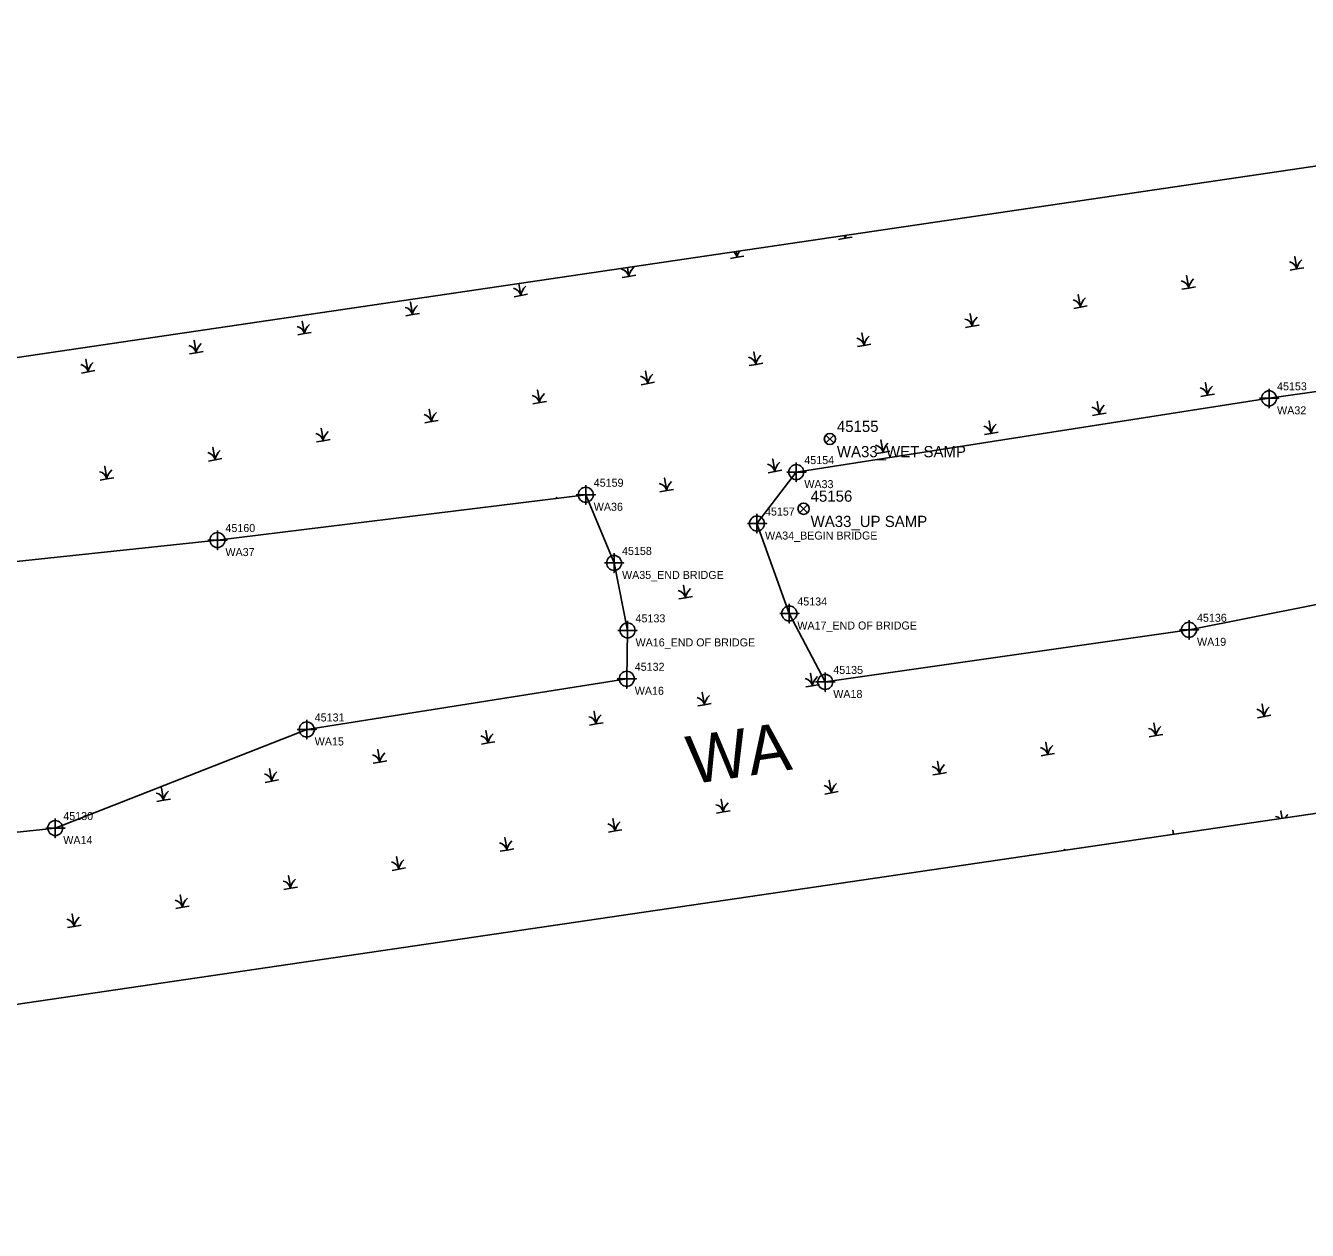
# Model space of a CAD drawing. Extents: x 2111078 to 2112659, y 581517 to 581899.
# Drawn here: x 2111868.3 to 2112268.6, y 581523.2 to 581899.2 of the extents above; entities that cross this region are included whole.
import ezdxf

# ---------------------------------------------------------------- set-up
doc = ezdxf.new("R2010")
doc.units = 0
for name, color, linetype in [('Default', 7, 'Continuous'), ('Exist Environmental Wetland Boundary', 7, 'Continuous'), ('Exist Environmental Wetland Boundary Cogo Comment', 7, 'Continuous'), ('Exist Environmental Wetland Boundary Cogo Number', 7, 'Continuous'), ('Exist Environmental Wetland Boundary Cogo Point CELL', 7, 'Continuous'), ('Exist Environmental Wetland Boundary Text', 7, 'Continuous'), ('Exist Hydro Swamp or Marsh', 7, 'Continuous')]:
    doc.layers.add(name, color=color, linetype=linetype)

msp = doc.modelspace()

# ---------------------------------------------------------------- linework, layer by layer
at = {"layer": 'Default'}
for p, q in [((2112120.71, 581771.41), (2112118.24, 581768.93)), ((2112118.24, 581771.41), (2112120.71, 581768.93)), ((2112112.51, 581749.62), (2112110.03, 581747.15)), ((2112110.03, 581749.62), (2112112.51, 581747.15))]:
    msp.add_line(p, q, dxfattribs=at)
msp.add_lwpolyline([(2111089.87, 581523.16), (2111077.52, 581722.78), (2111579.66, 581753.48), (2112568.99, 581899.18), (2112598.13, 581701.32), (2111600.4, 581554.74), (2111516.52, 581549.55)], close=True, dxfattribs=at)
for centre in [(2112119.47, 581770.17), (2112111.27, 581748.39)]:
    msp.add_circle(centre, 1.75, dxfattribs=at)
at = {"layer": 'Exist Environmental Wetland Boundary'}
for points in [[(2112579.95, 581824.73), (2112443.39, 581809.13), (2112256.64, 581782.86), (2112109, 581759.83), (2112096.72, 581743.78), (2112106.82, 581715.7), (2112118.04, 581694.33), (2112231.63, 581710.61), (2112367.17, 581737.55), (2112425.86, 581731.24), (2112435.22, 581709.75), (2112484.9, 581686.89), (2112506.03, 581692.11), (2112548.3, 581765.77), (2112570.44, 581765.42), (2112537.9, 581733.37), (2112525.65, 581690.67)], [(2111819.27, 581586.89), (2111826.15, 581643.33), (2111877.59, 581648.73), (2111956.11, 581679.5), (2112056.05, 581695.32), (2112056.3, 581710.43), (2112052.08, 581731.48), (2112043.26, 581752.76), (2111928.23, 581738.62), (2111810.46, 581726.15), (2111700.26, 581705.05), (2111584.01, 581692.46), (2111561.53, 581686.62), (2111561.94, 581674.72), (2111580.7, 581632.54), (2111595.75, 581624.66), (2111698.44, 581639.38), (2111781.79, 581581.39)]]:
    msp.add_lwpolyline(points, dxfattribs=at)
at = {"layer": 'Exist Environmental Wetland Boundary Cogo Point CELL'}
for points in [[(2112256.64, 581785.86), (2112256.64, 581779.86), (2112256.64, 581782.86), (2112259.64, 581782.86), (2112253.64, 581782.86)], [(2112109, 581762.83), (2112109, 581756.83), (2112109, 581759.83), (2112112, 581759.83), (2112106, 581759.83)], [(2112043.25, 581755.76), (2112043.25, 581749.76), (2112043.25, 581752.76), (2112046.25, 581752.76), (2112040.25, 581752.76)], [(2112096.72, 581746.78), (2112096.72, 581740.78), (2112096.72, 581743.78), (2112099.72, 581743.78), (2112093.72, 581743.78)], [(2111928.23, 581741.62), (2111928.23, 581735.62), (2111928.23, 581738.62), (2111931.23, 581738.62), (2111925.23, 581738.62)], [(2112052.08, 581734.48), (2112052.08, 581728.48), (2112052.08, 581731.48), (2112055.08, 581731.48), (2112049.08, 581731.48)], [(2112106.82, 581718.7), (2112106.82, 581712.7), (2112106.82, 581715.7), (2112109.82, 581715.7), (2112103.82, 581715.7)], [(2112056.3, 581713.43), (2112056.3, 581707.43), (2112056.3, 581710.43), (2112059.3, 581710.43), (2112053.3, 581710.43)], [(2112231.63, 581713.61), (2112231.63, 581707.61), (2112231.63, 581710.61), (2112234.63, 581710.61), (2112228.63, 581710.61)], [(2112056.05, 581698.32), (2112056.05, 581692.32), (2112056.05, 581695.32), (2112059.05, 581695.32), (2112053.05, 581695.32)], [(2112118.04, 581697.33), (2112118.04, 581691.33), (2112118.04, 581694.33), (2112121.04, 581694.33), (2112115.04, 581694.33)], [(2111956.11, 581682.5), (2111956.11, 581676.5), (2111956.11, 581679.5), (2111959.11, 581679.5), (2111953.11, 581679.5)], [(2111877.59, 581651.73), (2111877.59, 581645.73), (2111877.59, 581648.73), (2111880.59, 581648.73), (2111874.59, 581648.73)]]:
    msp.add_lwpolyline(points, dxfattribs=at)
for centre in [(2112256.64, 581782.86), (2112109, 581759.83), (2112043.25, 581752.76), (2112096.72, 581743.78), (2111928.23, 581738.62), (2112052.08, 581731.48), (2112106.82, 581715.7), (2112056.3, 581710.43), (2112231.63, 581710.61), (2112056.05, 581695.32), (2112118.04, 581694.33), (2111956.11, 581679.5), (2111877.59, 581648.73)]:
    msp.add_circle(centre, 2.34, dxfattribs=at)
at = {"layer": 'Exist Hydro Swamp or Marsh'}
for points in [[(2112122.19, 581832.46), (2112124.3, 581832.83), (2112124.16, 581833.67)], [(2112124.16, 581833.67), (2112124.3, 581832.83), (2112126.42, 581833.21)], [(2112088.41, 581826.5), (2112090.52, 581826.88), (2112090.21, 581828.67)], [(2112090.21, 581828.67), (2112090.52, 581826.88), (2112092.64, 581827.25)], [(2112263.2, 581822.85), (2112265.32, 581823.23), (2112264.63, 581827.11), (2112265.32, 581823.23), (2112267.44, 581823.6)], [(2112054.63, 581820.55), (2112056.74, 581820.92), (2112056.26, 581823.67)], [(2112056.26, 581823.67), (2112056.74, 581820.92), (2112058.86, 581821.29)], [(2112020.85, 581814.59), (2112022.96, 581814.96), (2112022.31, 581818.67)], [(2112022.31, 581818.67), (2112022.96, 581814.96), (2112025.08, 581815.34)], [(2112229.42, 581816.9), (2112231.54, 581817.27), (2112230.85, 581821.16), (2112231.54, 581817.27), (2112233.66, 581817.64)], [(2112195.64, 581810.94), (2112197.76, 581811.31), (2112197.07, 581815.2), (2112197.76, 581811.31), (2112199.88, 581811.69)], [(2111987.07, 581808.63), (2111989.19, 581809.01), (2111988.5, 581812.89), (2111989.19, 581809.01), (2111991.3, 581809.38)], [(2111953.29, 581802.68), (2111955.41, 581803.05), (2111954.72, 581806.94), (2111955.41, 581803.05), (2111957.52, 581803.42)], [(2112161.86, 581804.99), (2112163.98, 581805.36), (2112163.29, 581809.24), (2112163.98, 581805.36), (2112166.1, 581805.73)], [(2112128.08, 581799.03), (2112130.2, 581799.4), (2112129.51, 581803.29), (2112130.2, 581799.4), (2112132.32, 581799.78)], [(2111919.51, 581796.72), (2111921.63, 581797.09), (2111920.94, 581800.98), (2111921.63, 581797.09), (2111923.74, 581797.47)], [(2111885.73, 581790.76), (2111887.85, 581791.14), (2111887.16, 581795.02), (2111887.85, 581791.14), (2111889.96, 581791.51)], [(2112094.3, 581793.07), (2112096.42, 581793.45), (2112095.73, 581797.33), (2112096.42, 581793.45), (2112098.54, 581793.82)], [(2112060.52, 581787.12), (2112062.64, 581787.49), (2112061.95, 581791.37), (2112062.64, 581787.49), (2112064.76, 581787.86)], [(2112235.31, 581783.47), (2112237.43, 581783.84), (2112236.75, 581787.73), (2112237.43, 581783.84), (2112239.55, 581784.21)], [(2112026.74, 581781.16), (2112028.86, 581781.53), (2112028.17, 581785.42), (2112028.86, 581781.53), (2112030.98, 581781.91)], [(2111992.96, 581775.2), (2111995.08, 581775.58), (2111994.39, 581779.46), (2111995.08, 581775.58), (2111997.2, 581775.95)], [(2112201.53, 581777.51), (2112203.65, 581777.89), (2112202.97, 581781.77), (2112203.65, 581777.89), (2112205.77, 581778.26)], [(2112167.76, 581771.56), (2112169.87, 581771.93), (2112169.19, 581775.81), (2112169.87, 581771.93), (2112171.99, 581772.3)], [(2111959.18, 581769.25), (2111961.3, 581769.62), (2111960.61, 581773.51), (2111961.3, 581769.62), (2111963.42, 581769.99)], [(2112133.98, 581765.6), (2112136.09, 581765.97), (2112135.41, 581769.86), (2112136.09, 581765.97), (2112138.21, 581766.35)], [(2111925.4, 581763.29), (2111927.52, 581763.66), (2111926.84, 581767.55), (2111927.52, 581763.66), (2111929.64, 581764.04)], [(2112100.2, 581759.64), (2112102.31, 581760.02), (2112101.63, 581763.9), (2112102.31, 581760.02), (2112104.43, 581760.39)], [(2111891.62, 581757.33), (2111893.74, 581757.71), (2111893.06, 581761.59), (2111893.74, 581757.71), (2111895.86, 581758.08)], [(2112066.42, 581753.69), (2112068.53, 581754.06), (2112067.85, 581757.95), (2112068.53, 581754.06), (2112070.65, 581754.43)], [(2112034.13, 581751.64), (2112034.07, 581751.99), (2112034.13, 581751.64)], [(2112072.31, 581720.26), (2112074.43, 581720.63), (2112073.74, 581724.52), (2112074.43, 581720.63), (2112076.55, 581721)], [(2112111.98, 581692.78), (2112114.1, 581693.16), (2112113.42, 581697.04), (2112114.1, 581693.16), (2112116.22, 581693.53)], [(2112078.2, 581686.83), (2112080.32, 581687.2), (2112079.64, 581691.09), (2112080.32, 581687.2), (2112082.44, 581687.57)], [(2112253, 581683.18), (2112255.12, 581683.55), (2112254.43, 581687.44), (2112255.12, 581683.55), (2112257.23, 581683.93)], [(2112044.43, 581680.87), (2112046.54, 581681.25), (2112045.86, 581685.13), (2112046.54, 581681.25), (2112048.66, 581681.62)], [(2112010.65, 581674.92), (2112012.76, 581675.29), (2112012.08, 581679.17), (2112012.76, 581675.29), (2112014.88, 581675.66)], [(2112219.22, 581677.22), (2112221.34, 581677.6), (2112220.65, 581681.48), (2112221.34, 581677.6), (2112223.45, 581677.97)], [(2112185.44, 581671.27), (2112187.56, 581671.64), (2112186.87, 581675.53), (2112187.56, 581671.64), (2112189.67, 581672.01)], [(2111976.87, 581668.96), (2111978.98, 581669.33), (2111978.3, 581673.22), (2111978.98, 581669.33), (2111981.1, 581669.71)], [(2111943.09, 581663), (2111945.2, 581663.38), (2111944.52, 581667.26), (2111945.2, 581663.38), (2111947.32, 581663.75)], [(2112151.66, 581665.31), (2112153.78, 581665.68), (2112153.09, 581669.57), (2112153.78, 581665.68), (2112155.89, 581666.06)], [(2112117.88, 581659.35), (2112120, 581659.73), (2112119.31, 581663.61), (2112120, 581659.73), (2112122.11, 581660.1)], [(2111909.31, 581657.05), (2111911.42, 581657.42), (2111910.74, 581661.31), (2111911.42, 581657.42), (2111913.54, 581657.79)], [(2112084.1, 581653.4), (2112086.22, 581653.77), (2112085.53, 581657.66), (2112086.22, 581653.77), (2112088.33, 581654.15)], [(2112260.72, 581651.75), (2112260.33, 581654.01), (2112260.72, 581651.75)], [(2112050.32, 581647.44), (2112052.44, 581647.82), (2112051.75, 581651.7), (2112052.44, 581647.82), (2112054.56, 581648.19)], [(2112016.54, 581641.49), (2112018.66, 581641.86), (2112017.97, 581645.74), (2112018.66, 581641.86), (2112020.78, 581642.23)], [(2112226.77, 581646.76), (2112226.55, 581648.05), (2112226.77, 581646.76)], [(2112192.82, 581641.77), (2112192.77, 581642.1), (2112192.82, 581641.77)], [(2111982.76, 581635.53), (2111984.88, 581635.9), (2111984.19, 581639.79), (2111984.88, 581635.9), (2111987, 581636.28)], [(2111948.98, 581629.57), (2111951.1, 581629.95), (2111950.41, 581633.83), (2111951.1, 581629.95), (2111953.22, 581630.32)], [(2111915.2, 581623.62), (2111917.32, 581623.99), (2111916.63, 581627.88), (2111917.32, 581623.99), (2111919.44, 581624.36)], [(2111881.42, 581617.66), (2111883.54, 581618.03), (2111882.85, 581621.92), (2111883.54, 581618.03), (2111885.66, 581618.41)]]:
    msp.add_lwpolyline(points, dxfattribs=at)
for centre, radius, start, end in [((2112121.32, 581832.08), 3.07, 14.1403, 30.5701), ((2112129.06, 581832.13), 4.81, 160.6216, 171.6222), ((2112087.54, 581826.12), 3.07, 14.1403, 52.2834), ((2112095.28, 581826.18), 4.81, 146.4858, 171.6222), ((2112270.07, 581822.53), 4.81, 132.1274, 171.6222), ((2112053.76, 581820.17), 3.07, 14.1403, 77.535), ((2112061.5, 581820.22), 4.81, 132.1274, 171.6222), ((2112262.34, 581822.48), 3.07, 14.1403, 77.535), ((2112228.56, 581816.52), 3.07, 14.1403, 77.535), ((2112236.29, 581816.57), 4.81, 132.1274, 171.6222), ((2112019.98, 581814.21), 3.07, 14.1403, 77.535), ((2112027.72, 581814.26), 4.81, 132.1274, 171.6222), ((2112202.51, 581810.61), 4.81, 132.1274, 171.6222), ((2111986.2, 581808.26), 3.07, 14.1403, 77.535), ((2111993.94, 581808.31), 4.81, 132.1274, 171.6222), ((2112194.78, 581810.56), 3.07, 14.1403, 77.535), ((2111960.16, 581802.35), 4.81, 132.1274, 171.6222), ((2112161, 581804.61), 3.07, 14.1403, 77.535), ((2112168.73, 581804.66), 4.81, 132.1274, 171.6222), ((2111952.42, 581802.3), 3.07, 14.1403, 77.535), ((2112134.95, 581798.7), 4.81, 132.1274, 171.6222), ((2111918.64, 581796.34), 3.07, 14.1403, 77.535), ((2111926.38, 581796.39), 4.81, 132.1274, 171.6222), ((2112127.22, 581798.65), 3.07, 14.1403, 77.535), ((2111892.6, 581790.44), 4.81, 132.1274, 171.6222), ((2112093.44, 581792.69), 3.07, 14.1403, 77.535), ((2112101.17, 581792.75), 4.81, 132.1274, 171.6222), ((2111884.86, 581790.39), 3.07, 14.1403, 77.535), ((2112067.39, 581786.79), 4.81, 132.1274, 171.6222), ((2112059.66, 581786.74), 3.07, 14.1403, 77.535), ((2112234.45, 581783.09), 3.07, 14.1403, 77.535), ((2112242.19, 581783.14), 4.81, 132.1274, 171.6222), ((2112025.88, 581780.78), 3.07, 14.1403, 77.535), ((2112033.61, 581780.83), 4.81, 132.1274, 171.6222), ((2111992.1, 581774.83), 3.07, 14.1403, 77.535), ((2111999.83, 581774.88), 4.81, 132.1274, 171.6222), ((2112200.67, 581777.13), 3.07, 14.1403, 77.535), ((2112208.41, 581777.19), 4.81, 132.1274, 171.6222), ((2112166.89, 581771.18), 3.07, 14.1403, 77.535), ((2112174.63, 581771.23), 4.81, 132.1274, 171.6222), ((2111958.32, 581768.87), 3.07, 14.1403, 77.535), ((2111966.05, 581768.92), 4.81, 132.1274, 171.6222), ((2111924.54, 581762.91), 3.07, 14.1403, 77.535), ((2111932.27, 581762.96), 4.81, 132.1274, 171.6222), ((2112133.11, 581765.22), 3.07, 14.1403, 77.535), ((2112140.85, 581765.27), 4.81, 132.1274, 171.6222), ((2112099.33, 581759.27), 3.07, 14.1403, 77.535), ((2112107.07, 581759.32), 4.81, 132.1274, 171.6222), ((2111890.76, 581756.96), 3.07, 14.1403, 77.535), ((2111898.5, 581757.01), 4.81, 132.1274, 171.6222), ((2112065.55, 581753.31), 3.07, 14.1403, 77.535), ((2112073.29, 581753.36), 4.81, 132.1274, 171.6222), ((2112071.45, 581719.88), 3.07, 14.1403, 77.535), ((2112079.18, 581719.93), 4.81, 132.1274, 171.6222), ((2112111.12, 581692.41), 3.07, 14.1403, 77.535), ((2112118.86, 581692.46), 4.81, 132.1274, 171.6222), ((2112085.08, 581686.5), 4.81, 132.1274, 171.6222), ((2112077.34, 581686.45), 3.07, 14.1403, 77.535), ((2112252.13, 581682.8), 3.07, 14.1403, 77.535), ((2112259.87, 581682.85), 4.81, 132.1274, 171.6222), ((2112043.56, 581680.49), 3.07, 14.1403, 77.535), ((2112051.3, 581680.54), 4.81, 132.1274, 171.6222), ((2112017.52, 581674.59), 4.81, 132.1274, 171.6222), ((2112218.35, 581676.85), 3.07, 14.1403, 77.535), ((2112226.09, 581676.9), 4.81, 132.1274, 171.6222), ((2112009.78, 581674.54), 3.07, 14.1403, 77.535), ((2112184.57, 581670.89), 3.07, 14.1403, 77.535), ((2112192.31, 581670.94), 4.81, 132.1274, 171.6222), ((2111976, 581668.58), 3.07, 14.1403, 77.535), ((2111983.74, 581668.63), 4.81, 132.1274, 171.6222), ((2111949.96, 581662.68), 4.81, 132.1274, 171.6222), ((2112150.8, 581664.93), 3.07, 14.1403, 77.535), ((2112158.53, 581664.98), 4.81, 132.1274, 171.6222), ((2111942.22, 581662.63), 3.07, 14.1403, 77.535), ((2112117.02, 581658.98), 3.07, 14.1403, 77.535), ((2112124.75, 581659.03), 4.81, 132.1274, 171.6222), ((2111908.44, 581656.67), 3.07, 14.1403, 77.535), ((2111916.18, 581656.72), 4.81, 132.1274, 171.6222), ((2112083.24, 581653.02), 3.07, 14.1403, 77.535), ((2112090.97, 581653.07), 4.81, 132.1274, 171.6222), ((2112049.46, 581647.06), 3.07, 14.1403, 77.535), ((2112057.19, 581647.12), 4.81, 132.1274, 171.6222), ((2112258.03, 581649.37), 3.07, 47.9571, 77.535), ((2112265.76, 581649.42), 4.81, 132.1274, 149.2113), ((2112015.68, 581641.11), 3.07, 14.1403, 77.535), ((2112023.41, 581641.16), 4.81, 132.1274, 171.6222), ((2111981.9, 581635.15), 3.07, 14.1403, 77.535), ((2111989.63, 581635.2), 4.81, 132.1274, 171.6222), ((2111948.12, 581629.2), 3.07, 14.1403, 77.535), ((2111955.85, 581629.25), 4.81, 132.1274, 171.6222), ((2111914.34, 581623.24), 3.07, 14.1403, 77.535), ((2111922.07, 581623.29), 4.81, 132.1274, 171.6222), ((2111880.56, 581617.28), 3.07, 14.1403, 77.535), ((2111888.29, 581617.33), 4.81, 132.1274, 171.6222)]:
    msp.add_arc(centre, radius, start, end, dxfattribs=at)

# ---------------------------------------------------------------- texts
at = {"layer": 'Default'}
for s, p in [('45155', (2112121.67, 581772.37)), ('WA33_WET SAMP', (2112121.67, 581764.47)), ('45156', (2112113.47, 581750.59)), ('WA33_UP SAMP', (2112113.47, 581742.69))]:
    msp.add_text(s, height=3.5, dxfattribs=at).set_placement(p)
at = {"layer": 'Exist Environmental Wetland Boundary Cogo Comment'}
for s, p in [('WA32', (2112259.14, 581777.86)), ('WA33', (2112111.5, 581754.83)), ('WA36', (2112045.75, 581747.76)), ('WA34_BEGIN BRIDGE', (2112099.22, 581738.78)), ('WA37', (2111930.73, 581733.62)), ('WA35_END BRIDGE', (2112054.58, 581726.48)), ('WA17_END OF BRIDGE', (2112109.32, 581710.7)), ('WA16_END OF BRIDGE', (2112058.8, 581705.43)), ('WA19', (2112234.13, 581705.61)), ('WA16', (2112058.55, 581690.32)), ('WA18', (2112120.54, 581689.33)), ('WA15', (2111958.61, 581674.5)), ('WA14', (2111880.09, 581643.73))]:
    msp.add_text(s, height=2.5, dxfattribs=at).set_placement(p)
at = {"layer": 'Exist Environmental Wetland Boundary Cogo Number'}
for s, p in [('45153', (2112259.14, 581785.36)), ('45154', (2112111.5, 581762.33)), ('45159', (2112045.75, 581755.26)), ('45157', (2112099.22, 581746.28)), ('45160', (2111930.73, 581741.12)), ('45158', (2112054.58, 581733.98)), ('45134', (2112109.32, 581718.2)), ('45133', (2112058.8, 581712.93)), ('45136', (2112234.13, 581713.11)), ('45132', (2112058.55, 581697.82)), ('45135', (2112120.54, 581696.83)), ('45131', (2111958.61, 581682)), ('45130', (2111880.09, 581651.23))]:
    msp.add_text(s, height=2.5, dxfattribs=at).set_placement(p)
at = {"layer": 'Exist Environmental Wetland Boundary Text'}
msp.add_text('WA', height=15, rotation=8.3579, dxfattribs=at).set_placement((2112076.08, 581662.36))

doc.saveas('drawing.dxf')
